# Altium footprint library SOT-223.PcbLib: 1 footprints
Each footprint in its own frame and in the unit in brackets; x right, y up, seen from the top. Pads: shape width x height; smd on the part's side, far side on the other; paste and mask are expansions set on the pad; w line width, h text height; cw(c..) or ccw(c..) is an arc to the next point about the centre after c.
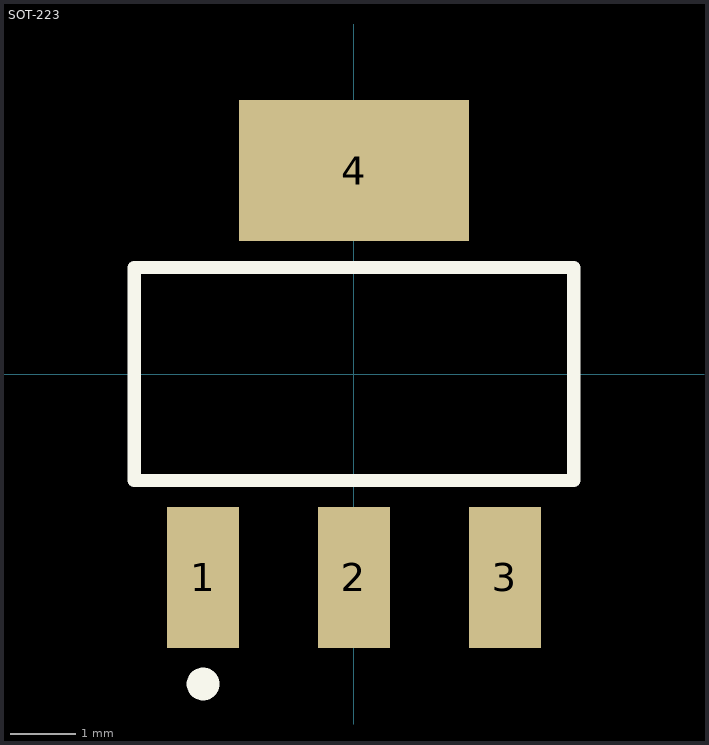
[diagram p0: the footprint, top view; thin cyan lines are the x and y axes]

## SOT-223 [mm]
height 1.778
pads (4):
  rect 1.1x2.15 smd: 1(-2.3,-3.1) 2(0,-3.1) 3(2.3,-3.1)
  rect 3.5x2.15 smd: 4(0,3.1)
Top Overlay:
  circle w0.25: c-2.3,-4.725 r0.125
  lines w0.2: -3.35,-1.625 3.35,-1.625 3.35,1.625 -3.35,1.625 -3.35,-1.625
